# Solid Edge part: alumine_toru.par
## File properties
Author: Romil
Template: iso part.par
Last saved by: Romil
Revision: 4
Application: Solid Edge
Accuracy: 0.990
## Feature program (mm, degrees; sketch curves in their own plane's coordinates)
lofted protrusion "unnamed LoftedProtrusion 1"
lofted protrusion "unnamed LoftedProtrusion 2"
lofted protrusion "unnamed LoftedProtrusion 3"
lofted protrusion "unnamed LoftedProtrusion 4"
lofted protrusion "unnamed LoftedProtrusion 5"
lofted protrusion "unnamed LoftedProtrusion 6"
lofted protrusion "unnamed LoftedProtrusion 7"
lofted protrusion "unnamed LoftedProtrusion 8"
lofted protrusion "unnamed LoftedProtrusion 9"
lofted protrusion "unnamed LoftedProtrusion 10"
lofted protrusion "unnamed LoftedProtrusion 11"
lofted protrusion "unnamed LoftedProtrusion 12"
lofted protrusion "unnamed LoftedProtrusion 13"
lofted protrusion "unnamed LoftedProtrusion 14"
lofted protrusion "unnamed LoftedProtrusion 15"
lofted protrusion "unnamed LoftedProtrusion 16"
lofted protrusion "unnamed LoftedProtrusion 17"
lofted protrusion "unnamed LoftedProtrusion 18"
lofted protrusion "unnamed LoftedProtrusion 19"
lofted protrusion "unnamed LoftedProtrusion 20"
lofted protrusion "unnamed LoftedProtrusion 21"
lofted protrusion "unnamed LoftedProtrusion 22"
lofted protrusion "unnamed LoftedProtrusion 23"
lofted protrusion "unnamed LoftedProtrusion 24"
lofted protrusion "unnamed LoftedProtrusion 25"
lofted protrusion "unnamed LoftedProtrusion 26"
lofted protrusion "unnamed LoftedProtrusion 27"
lofted protrusion "unnamed LoftedProtrusion 28"
lofted protrusion "unnamed LoftedProtrusion 29"
lofted protrusion "unnamed LoftedProtrusion 30"
lofted protrusion "unnamed LoftedProtrusion 31"
lofted protrusion "unnamed LoftedProtrusion 32"
lofted protrusion "unnamed LoftedProtrusion 33"
lofted protrusion "unnamed LoftedProtrusion 34"
lofted protrusion "unnamed LoftedProtrusion 35"
lofted protrusion "unnamed LoftedProtrusion 36"
lofted protrusion "unnamed LoftedProtrusion 37"
lofted protrusion "unnamed LoftedProtrusion 38"
lofted protrusion "unnamed LoftedProtrusion 39"
lofted protrusion "unnamed LoftedProtrusion 40"
lofted protrusion "unnamed LoftedProtrusion 41"
lofted protrusion "unnamed LoftedProtrusion 42"
lofted protrusion "unnamed LoftedProtrusion 43"
lofted protrusion "unnamed LoftedProtrusion 44"
lofted protrusion "unnamed LoftedProtrusion 45"
lofted protrusion "unnamed LoftedProtrusion 46"
lofted protrusion "unnamed LoftedProtrusion 47"
lofted protrusion "unnamed LoftedProtrusion 48"
lofted protrusion "unnamed LoftedProtrusion 49"
lofted protrusion "unnamed LoftedProtrusion 50"
lofted protrusion "unnamed LoftedProtrusion 51"
lofted protrusion "unnamed LoftedProtrusion 52"
lofted protrusion "unnamed LoftedProtrusion 53"
lofted protrusion "unnamed LoftedProtrusion 54"
lofted protrusion "unnamed LoftedProtrusion 55"
lofted protrusion "unnamed LoftedProtrusion 56"
lofted protrusion "unnamed LoftedProtrusion 57"
lofted protrusion "unnamed LoftedProtrusion 58"
lofted protrusion "unnamed LoftedProtrusion 59"
lofted protrusion "unnamed LoftedProtrusion 60"
lofted protrusion "unnamed LoftedProtrusion 61"
lofted protrusion "unnamed LoftedProtrusion 62"
lofted protrusion "unnamed LoftedProtrusion 63"
lofted protrusion "unnamed LoftedProtrusion 64"
lofted protrusion "unnamed LoftedProtrusion 65"
lofted protrusion "unnamed LoftedProtrusion 66"
lofted protrusion "unnamed LoftedProtrusion 67"
lofted protrusion "unnamed LoftedProtrusion 68"
lofted protrusion "unnamed LoftedProtrusion 69"
lofted protrusion "unnamed LoftedProtrusion 70"
lofted protrusion "unnamed LoftedProtrusion 71"
lofted protrusion "unnamed LoftedProtrusion 72"
lofted protrusion "unnamed LoftedProtrusion 73"
lofted protrusion "unnamed LoftedProtrusion 74"
lofted protrusion "unnamed LoftedProtrusion 75"
lofted protrusion "unnamed LoftedProtrusion 76"
lofted protrusion "unnamed LoftedProtrusion 77"
lofted protrusion "unnamed LoftedProtrusion 78"
lofted protrusion "unnamed LoftedProtrusion 79"
lofted protrusion "unnamed LoftedProtrusion 80"
lofted protrusion "unnamed LoftedProtrusion 81"
lofted protrusion "unnamed LoftedProtrusion 82"
lofted protrusion "unnamed LoftedProtrusion 83"
lofted protrusion "unnamed LoftedProtrusion 84"
lofted protrusion "unnamed LoftedProtrusion 85"
lofted protrusion "unnamed LoftedProtrusion 86"
lofted protrusion "unnamed LoftedProtrusion 87"
lofted protrusion "unnamed LoftedProtrusion 88"
lofted protrusion "unnamed LoftedProtrusion 89"
lofted protrusion "unnamed LoftedProtrusion 90"
lofted protrusion "unnamed LoftedProtrusion 91"
lofted protrusion "unnamed LoftedProtrusion 92"
lofted protrusion "unnamed LoftedProtrusion 93"
lofted protrusion "unnamed LoftedProtrusion 94"
lofted protrusion "unnamed LoftedProtrusion 95"
lofted protrusion "unnamed LoftedProtrusion 96"
lofted protrusion "unnamed LoftedProtrusion 97"
lofted protrusion "unnamed LoftedProtrusion 98"
lofted protrusion "unnamed LoftedProtrusion 99"
lofted protrusion "unnamed LoftedProtrusion 100"
lofted protrusion "unnamed LoftedProtrusion 101"
swept protrusion "SweptProtrusion_1"
fillet "Round_1" radius 0.2
fillet "unnamed Round 1"
fillet "unnamed Round 2"
fillet "unnamed Round 3"
fillet "unnamed Round 4"
fillet "unnamed Round 5"
fillet "unnamed Round 6"
fillet "unnamed Round 7"
fillet "unnamed Round 8"
fillet "unnamed Round 9"
fillet "unnamed Round 10"
fillet "unnamed Round 11"
fillet "unnamed Round 12"
fillet "unnamed Round 13"
fillet "unnamed Round 14"
fillet "unnamed Round 15"
fillet "unnamed Round 16"
fillet "unnamed Round 17"
fillet "unnamed Round 18"
fillet "unnamed Round 19"
fillet "unnamed Round 20"
fillet "unnamed Round 21"
fillet "unnamed Round 22"
fillet "unnamed Round 23"
fillet "unnamed Round 24"
fillet "unnamed Round 25"
fillet "unnamed Round 26"
fillet "unnamed Round 27"
fillet "unnamed Round 28"
fillet "unnamed Round 29"
fillet "unnamed Round 30"
fillet "unnamed Round 31"
fillet "unnamed Round 32"
fillet "unnamed Round 33"
fillet "unnamed Round 34"
fillet "unnamed Round 35"
fillet "unnamed Round 36"
fillet "unnamed Round 37"
fillet "unnamed Round 38"
fillet "unnamed Round 39"
fillet "unnamed Round 40"
fillet "unnamed Round 41"
fillet "unnamed Round 42"
fillet "unnamed Round 43"
fillet "unnamed Round 44"
fillet "unnamed Round 45"
fillet "unnamed Round 46"
fillet "unnamed Round 47"
fillet "unnamed Round 48"
fillet "unnamed Round 49"
fillet "unnamed Round 50"
fillet "unnamed Round 51"
fillet "unnamed Round 52"
fillet "unnamed Round 53"
fillet "unnamed Round 54"
fillet "unnamed Round 55"
fillet "unnamed Round 56"
fillet "unnamed Round 57"
fillet "unnamed Round 58"
fillet "unnamed Round 59"
fillet "unnamed Round 60"
fillet "unnamed Round 61"
fillet "unnamed Round 62"
fillet "unnamed Round 63"
fillet "unnamed Round 64"
fillet "unnamed Round 65"
fillet "unnamed Round 66"
fillet "unnamed Round 67"
fillet "unnamed Round 68"
fillet "unnamed Round 69"
fillet "unnamed Round 70"
fillet "unnamed Round 71"
fillet "unnamed Round 72"
fillet "unnamed Round 73"
fillet "unnamed Round 74"
fillet "unnamed Round 75"
fillet "unnamed Round 76"
fillet "unnamed Round 77"
fillet "unnamed Round 78"
fillet "unnamed Round 79"
fillet "unnamed Round 80"
fillet "unnamed Round 81"
fillet "unnamed Round 82"
fillet "unnamed Round 83"
fillet "unnamed Round 84"
fillet "unnamed Round 85"
fillet "unnamed Round 86"
fillet "unnamed Round 87"
fillet "unnamed Round 88"
fillet "unnamed Round 89"
fillet "unnamed Round 90"
fillet "unnamed Round 91"
fillet "unnamed Round 92"
fillet "unnamed Round 93"
fillet "unnamed Round 94"
fillet "unnamed Round 95"
fillet "unnamed Round 96"
fillet "unnamed Round 97"
fillet "unnamed Round 98"
fillet "unnamed Round 99"
fillet "unnamed Round 100"
thinwall "Thinwall_1"  Thickness = 0.2 mm
Other named dimensions: "ExtrudedSurface_1": FiniteDepth = 382.8358 mm | "ExtrudedSurface_2": FiniteDepth = 118.3047 mm | "Pattern_1": XDirCount = 101; XDirSpacing = 2.2061 mm | "Pattern_2": XDirCount = 101; XDirSpacing = 2.2061 mm
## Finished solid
Body 1: solid body, 1010 faces, 1009 edges, 0 vertices.
  Faces by surface: plane 402, cylinder 298, torus 202, offset 54, spline 54
  Edges by curve: circle 796, intersection 212, curve on surface 1
Body 2: sheet body, 4 faces, 13 edges, 10 vertices.
  Faces by surface: cylinder 2, plane 2
  Edges by curve: line 9, circle 4
Body 3: sheet body, 1 face, 4 edges, 4 vertices.
  Faces by surface: plane 1
  Edges by curve: line 4
Bounding box of the edges (mm; curved faces can reach further): 81.469 x 382.836 x 118.305, from (-40.7345, -191.4179, -59.1524) to (40.7345, 191.4179, 59.1524).
Cylindrical faces by radius (mm): R2.4 x48, R2.6 x48, R3.35 x101, R3.55 x101, R36.1861 x2
Toroidal faces (ring radius, tube radius in mm): R3.35 r0.2 x202
Planar faces by outward normal: +x 2, +y 95, -x 2, -y 95, oblique 208
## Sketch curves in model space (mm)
circle centre (37.1833, -41.9763, 15.5246) radius 2.6
circle centre (37.1833, -41.9763, 15.5246) radius 3.55
circle centre (37.1833, -43.0763, 15.5246) radius 3.55
circle centre (37.1833, -43.0763, 15.5246) radius 2.6
line (37.1833, -41.9763, 0) -> (37.1833, -94.4434, 0)
arc centre (0.9972, -94.4434, 0) radius 36.1861 from (37.1833, -94.4434, 0) through (25.451, -121.1164, 0) to (0, -130.6158, 0)
arc centre (-0.9972, -94.4434, 0) radius 36.1861 from (-37.1833, -94.4434, 0) through (-25.451, -121.1164, 0) to (0, -130.6158, 0)
line (-37.1833, -41.9763, 0) -> (-37.1833, -94.4434, 0)
line (37.1833, 0, 15.5246) -> (-37.1833, 0, 15.5246)
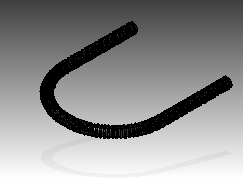
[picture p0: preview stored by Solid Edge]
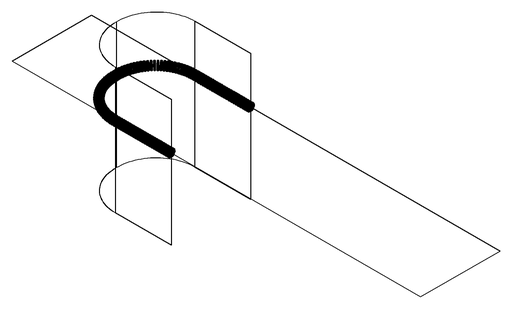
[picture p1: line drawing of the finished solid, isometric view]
